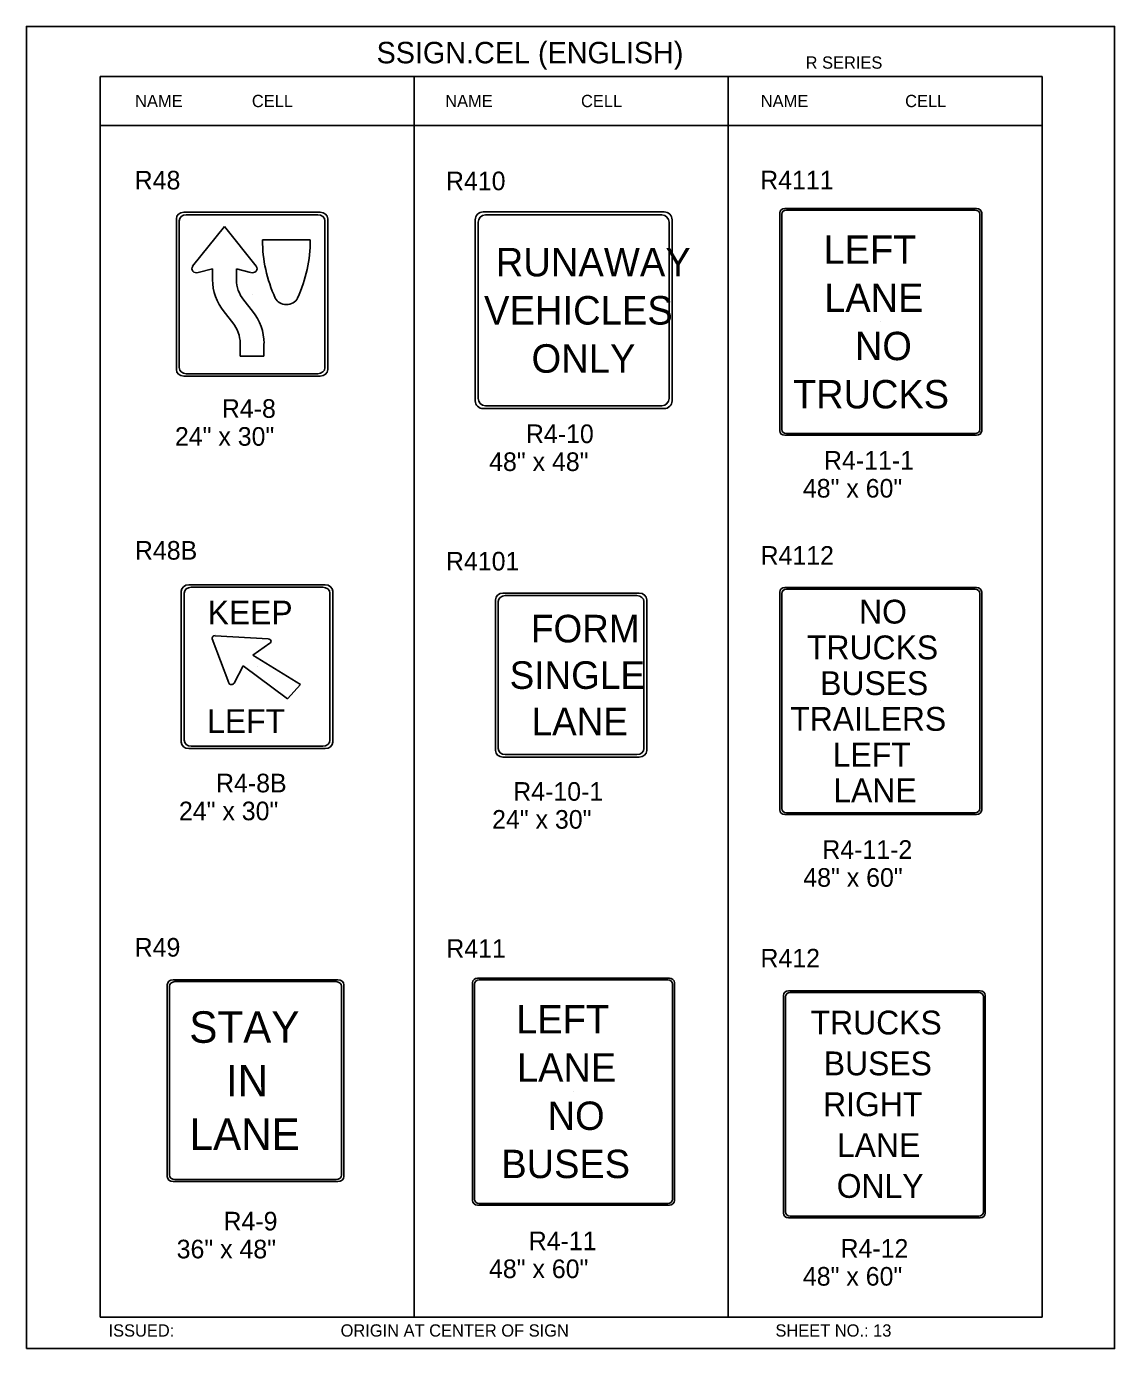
# Model space of a CAD drawing. Extents: x -5299 to 22597, y -19549 to -1808.
# Drawn here: x -5299 to -4598, y -5466 to -4614 of the extents above; entities that cross this region are included whole.
import ezdxf

# ---------------------------------------------------------------- set-up
doc = ezdxf.new("R2010")
doc.units = 0
for name, color, linetype in [('Level 1', 7, 'Continuous'), ('Level 2', 7, 'Continuous'), ('Level 3', 7, 'Continuous'), ('Level 63', 7, 'Continuous')]:
    doc.layers.add(name, color=color, linetype=linetype)

msp = doc.modelspace()

# ---------------------------------------------------------------- linework, layer by layer
at = {"layer": 'Level 1'}
for p, q in [((-4644.53, -4645.77), (-5251.55, -4645.77)), ((-5251.55, -4645.77), (-5251.55, -5445.77)), ((-5049.21, -4645.77), (-5049.21, -5445.77)), ((-4846.87, -4645.77), (-4846.87, -5445.77)), ((-4644.53, -4645.77), (-4644.53, -5445.77)), ((-4644.53, -4677.44), (-5251.55, -4677.44)), ((-5200.66, -4833.56), (-5200.66, -4738.86)), ((-5196.15, -4734.95), (-5111.26, -4734.95)), ((-5106.75, -4738.86), (-5106.75, -4833.56)), ((-5003.32, -4735.07), (-4889.68, -4735.07)), ((-4812.44, -4873.4), (-4812.44, -4734.69)), ((-4809.43, -4731.98), (-4687.82, -4731.98)), ((-4684.81, -4734.69), (-4684.81, -4873.4)), ((-5171.46, -4742.49), (-5191.98, -4768.19)), ((-5151.01, -4768.19), (-5171.46, -4742.49)), ((-5008.01, -4853.41), (-5008.01, -4739.77)), ((-4884.98, -4739.77), (-4884.98, -4853.41)), ((-5116.22, -4751.22), (-5146.96, -4751.22)), ((-5188.39, -4772.32), (-5179.18, -4769.88)), ((-5179.18, -4769.88), (-5179.18, -4776.85)), ((-5163.81, -4776.85), (-5163.81, -4769.88)), ((-5163.81, -4769.88), (-5154.6, -4772.32)), ((-5153.43, -4797.13), (-5159.05, -4790.1)), ((-5153.71, -4786.21), (-5153.71, -4786.21)), ((-5171.77, -4797.61), (-5166.15, -4804.64)), ((-4946.5, -4796.59), (-4946.5, -4796.59)), ((-4748.63, -4804.05), (-4748.63, -4804.05)), ((-5161.39, -4817.89), (-5161.39, -4826.21)), ((-5146.02, -4826.21), (-5146.02, -4817.89)), ((-5161.39, -4826.21), (-5146.02, -4826.21)), ((-5111.26, -4837.47), (-5196.15, -4837.47)), ((-5008.01, -4853.41), (-5008.01, -4853.41)), ((-4889.68, -4858.1), (-5003.32, -4858.1)), ((-4687.82, -4876.11), (-4809.43, -4876.11)), ((-5192.95, -4975.1), (-5108.06, -4975.1)), ((-4809.43, -4976.41), (-4687.82, -4976.41)), ((-5197.46, -5073.72), (-5197.46, -4979.01)), ((-5103.55, -4979.01), (-5103.55, -5073.72)), ((-4995.1, -5079.13), (-4995.1, -4984.42)), ((-4990.59, -4980.51), (-4905.7, -4980.51)), ((-4901.19, -4984.42), (-4901.19, -5079.13)), ((-4812.44, -5117.82), (-4812.44, -4979.11)), ((-4684.81, -4979.11), (-4684.81, -5117.82)), ((-5179.33, -5008.44), (-5168.72, -5036.84)), ((-5143.28, -5008.44), (-5177.46, -5006.41)), ((-5153.11, -5018.98), (-5142.19, -5011.28)), ((-5122.53, -5037.78), (-5153.11, -5018.98)), ((-5165.28, -5036.97), (-5159.35, -5025.88)), ((-5159.35, -5025.88), (-5130.95, -5046.98)), ((-5150.5, -5026.36), (-5150.5, -5026.36)), ((-4948.14, -5031.77), (-4948.14, -5031.77)), ((-5130.95, -5046.98), (-5122.53, -5037.78)), ((-4748.63, -5048.47), (-4748.63, -5048.47)), ((-5108.06, -5077.62), (-5192.95, -5077.62)), ((-4905.7, -5083.03), (-4990.59, -5083.03)), ((-4687.82, -5120.53), (-4809.43, -5120.53)), ((-5206.97, -5354.03), (-5206.97, -5232.42)), ((-5203.46, -5229.41), (-5099.5, -5229.41)), ((-5095.99, -5232.42), (-5095.99, -5354.03)), ((-5010.41, -5369.65), (-5010.41, -5230.94)), ((-5007.4, -5228.24), (-4885.79, -5228.24)), ((-4882.78, -5230.94), (-4882.78, -5369.65)), ((-4811.32, -5378.68), (-4811.32, -5238.23)), ((-4810.11, -5377.81), (-4810.11, -5239.1)), ((-4808.06, -5235.31), (-4684.52, -5235.31)), ((-4807.1, -5236.4), (-4685.49, -5236.4)), ((-4682.48, -5239.1), (-4682.48, -5377.81)), ((-4681.27, -5238.23), (-4681.27, -5378.68)), ((-5151.48, -5293.23), (-5151.48, -5293.23)), ((-4946.6, -5300.3), (-4946.6, -5300.3)), ((-4746.29, -5308.46), (-4746.29, -5308.46)), ((-5099.5, -5357.04), (-5203.46, -5357.04)), ((-4885.79, -5372.36), (-5007.4, -5372.36)), ((-4684.52, -5381.61), (-4808.06, -5381.61)), ((-4685.49, -5380.52), (-4807.1, -5380.52)), ((-5251.55, -5445.77), (-4644.53, -5445.77))]:
    msp.add_line(p, q, dxfattribs=at)
for centre, start, end in [((-5003.32, -4739.77), 90, 180), ((-4889.68, -4739.77), 0, 90), ((-5003.32, -4853.41), 180, 270), ((-4889.68, -4853.41), 270, 0)]:
    msp.add_arc(centre, 4.69, start, end, dxfattribs=at)
for centre, major_axis, ratio, start_param, end_param in [((-5196.15, -4738.86), (-4.51, 0), 0.866667, 4.712389, 6.283185), ((-5111.26, -4738.86), (-4.51, 0), 0.866667, 3.141593, 4.712389), ((-4809.43, -4734.69), (-3.01, 0), 0.9, 4.712389, 6.283185), ((-4687.82, -4734.69), (-3.01, 0), 0.9, 3.141593, 4.712389), ((-5031.47, -4751.56), (-115.48, 0), 0.866667, 6.279909, 6.663033), ((-5231.25, -4751.64), (115.05, 0), 0.866667, 5.902613, 6.287187), ((-5189.26, -4769.66), (-3.2, 0), 0.866667, 5.710118, 8.143254), ((-5153.67, -4769.66), (3.2, 0), 0.866667, 4.423116, 6.856252), ((-5136.67, -4776.83), (42.49, 0), 0.866667, 3.14236, 3.740294), ((-5136.89, -4776.86), (26.88, 0), 0.866667, 3.141339, 3.744924), ((-5131.57, -4786.23), (7.68, 0), 0.866667, 3.517117, 5.907661), ((-5188.29, -4817.88), (-42.29, 0), 0.866667, 3.141593, 3.744195), ((-5188.15, -4817.87), (26.77, 0), 0.866667, 6.282648, 6.891725), ((-5196.15, -4833.56), (4.51, 0), 0.866667, 3.141593, 4.712389), ((-5111.26, -4833.56), (4.51, 0), 0.866667, 4.712389, 6.283185), ((-4809.43, -4873.4), (3.01, 0), 0.9, 3.141593, 4.712389), ((-4687.82, -4873.4), (3.01, 0), 0.9, 4.712389, 6.283185), ((-5192.95, -4979.01), (-4.51, 0), 0.866667, 4.712389, 6.283185), ((-5108.06, -4979.01), (-4.51, 0), 0.866667, 3.141593, 4.712389), ((-4809.43, -4979.11), (-3.01, 0), 0.9, 4.712389, 6.283185), ((-4687.82, -4979.11), (-3.01, 0), 0.9, 3.141593, 4.712389), ((-4990.59, -4984.42), (-4.51, 0), 0.866667, 4.712389, 6.283185), ((-4905.7, -4984.42), (-4.51, 0), 0.866667, 3.141593, 4.712389), ((-5177.58, -5007.97), (-1.89, 0), 0.866667, 4.637334, 6.588204), ((-5143.3, -5010.03), (1.88, 0), 0.866667, 5.375922, 7.805476), ((-5166.98, -5036.3), (1.88, 0), 0.866667, 3.443944, 5.86527), ((-5192.95, -5073.72), (4.51, 0), 0.866667, 3.141593, 4.712389), ((-5108.06, -5073.72), (4.51, 0), 0.866667, 4.712389, 6.283185), ((-4990.59, -5079.13), (4.51, 0), 0.866667, 3.141593, 4.712389), ((-4905.7, -5079.13), (4.51, 0), 0.866667, 4.712389, 6.283185), ((-4809.43, -5117.83), (3.01, 0), 0.9, 3.141593, 4.712389), ((-4687.82, -5117.83), (3.01, 0), 0.9, 4.712389, 6.283185), ((-5203.46, -5232.42), (-3.51, 0), 0.857082, 4.712389, 6.283185), ((-5099.5, -5232.42), (-3.51, 0), 0.857082, 3.141593, 4.712389), ((-5007.4, -5230.94), (-3.01, 0), 0.9, 4.712389, 6.283185), ((-4885.79, -5230.94), (-3.01, 0), 0.9, 3.141593, 4.712389), ((-4808.06, -5238.24), (-3.25, 0), 0.9, 4.712389, 6.283185), ((-4807.1, -5239.1), (-3.01, 0), 0.9, 4.712389, 6.283185), ((-4685.49, -5239.1), (-3.01, 0), 0.9, 3.141593, 4.712389), ((-4684.52, -5238.24), (-3.25, 0), 0.9, 3.141593, 4.712389), ((-5203.46, -5354.03), (3.51, 0), 0.857082, 3.141593, 4.712389), ((-5099.5, -5354.03), (3.51, 0), 0.857082, 4.712389, 6.283185), ((-5007.4, -5369.66), (3.01, 0), 0.9, 3.141593, 4.712389), ((-4885.79, -5369.66), (3.01, 0), 0.9, 4.712389, 6.283185), ((-4807.1, -5377.81), (3.01, 0), 0.9, 3.141593, 4.712389), ((-4685.49, -5377.81), (3.01, 0), 0.9, 4.712389, 6.283185), ((-4808.06, -5378.68), (3.25, 0), 0.9, 3.141593, 4.712389), ((-4684.52, -5378.68), (3.25, 0), 0.9, 4.712389, 6.283185)]:
    msp.add_ellipse(centre, major_axis=major_axis, ratio=ratio, start_param=start_param, end_param=end_param, dxfattribs=at)
at = {"layer": 'Level 3'}
for p, q in [((-5202.47, -4834.82), (-5202.47, -4737.61)), ((-5197.6, -4733.38), (-5109.82, -4733.38)), ((-5104.94, -4737.61), (-5104.94, -4834.82)), ((-5009.89, -4854.91), (-5009.89, -4738.26)), ((-5004.82, -4733.19), (-4888.17, -4733.19)), ((-4883.1, -4738.26), (-4883.1, -4854.91)), ((-4813.65, -4733.82), (-4813.65, -4874.27)), ((-4686.86, -4730.9), (-4810.4, -4730.9)), ((-4683.61, -4874.27), (-4683.61, -4733.82)), ((-5109.82, -4839.04), (-5197.6, -4839.04)), ((-4888.17, -4859.98), (-5004.82, -4859.98)), ((-4810.4, -4877.19), (-4686.86, -4877.19)), ((-5199.27, -4977.76), (-5199.27, -5074.97)), ((-5106.61, -4973.53), (-5194.39, -4973.53)), ((-5101.74, -5074.97), (-5101.74, -4977.76)), ((-4810.4, -4975.32), (-4686.86, -4975.32)), ((-4996.91, -5080.38), (-4996.91, -4983.17)), ((-4992.03, -4978.94), (-4904.26, -4978.94)), ((-4899.38, -4983.17), (-4899.38, -5080.38)), ((-4813.65, -5118.69), (-4813.65, -4978.25)), ((-4683.61, -4978.25), (-4683.61, -5118.69)), ((-5194.39, -5079.19), (-5106.61, -5079.19)), ((-4904.26, -5084.6), (-4992.03, -5084.6)), ((-4686.86, -5121.62), (-4810.4, -5121.62)), ((-5208.38, -5355), (-5208.38, -5231.46)), ((-5204.58, -5228.21), (-5098.38, -5228.21)), ((-5094.58, -5231.46), (-5094.58, -5355)), ((-5011.62, -5370.52), (-5011.62, -5230.08)), ((-5008.37, -5227.15), (-4884.83, -5227.15)), ((-4881.58, -5230.08), (-4881.58, -5370.52)), ((-4811.32, -5378.68), (-4811.32, -5238.23)), ((-4808.06, -5235.31), (-4684.52, -5235.31)), ((-4681.27, -5238.23), (-4681.27, -5378.68)), ((-5098.38, -5358.25), (-5204.58, -5358.25)), ((-4884.83, -5373.45), (-5008.37, -5373.45)), ((-4684.52, -5381.61), (-4808.06, -5381.61))]:
    msp.add_line(p, q, dxfattribs=at)
for centre, start, end in [((-5004.82, -4738.26), 90, 180), ((-4888.17, -4738.26), 0, 90), ((-5004.82, -4854.91), 180, 270), ((-4888.17, -4854.91), 270, 0)]:
    msp.add_arc(centre, 5.07, start, end, dxfattribs=at)
for centre, major_axis, ratio, start_param, end_param in [((-5197.6, -4737.61), (-4.88, 0), 0.866667, 4.712389, 6.283185), ((-5109.82, -4737.61), (-4.88, 0), 0.866667, 3.141593, 4.712389), ((-4810.4, -4733.82), (-3.25, 0), 0.9, 4.712389, 6.283185), ((-4686.86, -4733.82), (-3.25, 0), 0.9, 3.141593, 4.712389), ((-5197.6, -4834.82), (4.88, 0), 0.866667, 3.141593, 4.712389), ((-5109.82, -4834.82), (4.88, 0), 0.866667, 4.712389, 6.283185), ((-4810.4, -4874.27), (3.25, 0), 0.9, 3.141593, 4.712389), ((-4686.86, -4874.27), (3.25, 0), 0.9, 4.712389, 6.283185), ((-5194.39, -4977.76), (-4.88, 0), 0.866667, 4.712389, 6.283185), ((-5106.61, -4977.76), (-4.88, 0), 0.866667, 3.141593, 4.712389), ((-4810.4, -4978.25), (-3.25, 0), 0.9, 4.712389, 6.283185), ((-4686.86, -4978.25), (-3.25, 0), 0.9, 3.141593, 4.712389), ((-4992.03, -4983.17), (-4.88, 0), 0.866667, 4.712389, 6.283185), ((-4904.26, -4983.17), (-4.88, 0), 0.866667, 3.141593, 4.712389), ((-5194.39, -5074.97), (4.88, 0), 0.866667, 3.141593, 4.712389), ((-5106.61, -5074.97), (4.88, 0), 0.866667, 4.712389, 6.283185), ((-4992.03, -5080.38), (4.88, 0), 0.866667, 3.141593, 4.712389), ((-4904.26, -5080.38), (4.88, 0), 0.866667, 4.712389, 6.283185), ((-4810.4, -5118.69), (3.25, 0), 0.9, 3.141593, 4.712389), ((-4686.86, -5118.69), (3.25, 0), 0.9, 4.712389, 6.283185), ((-5204.58, -5231.46), (-3.79, 0), 0.857082, 4.712389, 6.283185), ((-5098.38, -5231.46), (-3.79, 0), 0.857082, 3.141593, 4.712389), ((-5008.37, -5230.08), (-3.25, 0), 0.9, 4.712389, 6.283185), ((-4884.83, -5230.08), (-3.25, 0), 0.9, 3.141593, 4.712389), ((-4808.06, -5238.24), (-3.25, 0), 0.9, 4.712389, 6.283185), ((-4684.52, -5238.24), (-3.25, 0), 0.9, 3.141593, 4.712389), ((-5204.58, -5355), (3.79, 0), 0.857082, 3.141593, 4.712389), ((-5098.38, -5355), (3.79, 0), 0.857082, 4.712389, 6.283185), ((-5008.37, -5370.52), (3.25, 0), 0.9, 3.141593, 4.712389), ((-4884.83, -5370.52), (3.25, 0), 0.9, 4.712389, 6.283185), ((-4808.06, -5378.68), (3.25, 0), 0.9, 3.141593, 4.712389), ((-4684.52, -5378.68), (3.25, 0), 0.9, 4.712389, 6.283185)]:
    msp.add_ellipse(centre, major_axis=major_axis, ratio=ratio, start_param=start_param, end_param=end_param, dxfattribs=at)
at = {"layer": 'Level 63'}
msp.add_lwpolyline([(-5299.05, -5465.96), (-4598.01, -5465.96), (-4598.01, -4613.58), (-5299.05, -4613.58)], close=True, dxfattribs=at)

# ---------------------------------------------------------------- texts
at = {"layer": 'Level 1'}
for s, height, p in [('LEFT', 18.287, (-4785.5, -4766.56)), ('RUNAWAY', 18.385, (-4996.69, -4774.72)), ('LANE', 18.287, (-4785.03, -4797.64)), ('VEHICLES', 18.385, (-5004.24, -4805.78)), ('NO', 18.287, (-4765.27, -4828.73)), ('ONLY', 18.385, (-4973.63, -4836.84)), ('TRUCKS', 18.287, (-4805.18, -4859.82)), ('KEEP', 15.321, (-5182.24, -4999.11)), ('NO', 15.361, (-4762.6, -4998.55)), ('FORM', 17.779, (-4974.01, -5010.69)), ('TRUCKS', 15.361, (-4796.13, -5021.59)), ('SINGLE', 17.779, (-4987.73, -5040.66)), ('BUSES', 15.361, (-4787.67, -5044.63)), ('LEFT', 15.321, (-5182.59, -5069.08)), ('LANE', 17.779, (-4973.62, -5070.63)), ('TRAILERS', 15.361, (-4806.93, -5067.67)), ('LEFT', 15.361, (-4779.6, -5090.71)), ('LANE', 15.361, (-4779.2, -5113.75)), ('STAY', 20.319, (-5194.13, -5268.84)), ('LEFT', 18.287, (-4983.47, -5262.81)), ('TRUCKS', 15.361, (-4793.8, -5263.47)), ('LANE', 18.287, (-4982.99, -5293.9)), ('BUSES', 15.361, (-4785.34, -5289.8)), ('IN', 20.319, (-5170.52, -5303.39)), ('RIGHT', 15.361, (-4785.74, -5316.14)), ('NO', 18.287, (-4963.23, -5324.99)), ('LANE', 20.319, (-5193.95, -5337.93)), ('LANE', 15.361, (-4776.87, -5342.47)), ('BUSES', 18.287, (-4993.07, -5356.07)), ('ONLY', 15.361, (-4777, -5368.8))]:
    msp.add_text(s, height=height, dxfattribs=at).set_placement(p)
at = {"layer": 'Level 2'}
for s, p in [('R48', (-5229.31, -4718.68)), ('R410', (-5028.76, -4719.19)), ('R4111', (-4826.31, -4718.62)), ('R48B', (-5229.17, -4957.34)), ('R4101', (-5028.76, -4964.32)), ('R4112', (-4826.08, -4960.62)), ('R49', (-5229.32, -5213.26)), ('R411', (-5028.53, -5214.03)), ('R412', (-4826.14, -5220.27))]:
    msp.add_text(s, height=12, dxfattribs=at).set_placement(p)
at = {"layer": 'Level 3'}
for s, height, p in [('SSIGN.CEL (ENGLISH)', 13.8566, (-5073.47, -4637.38)), ('R SERIES', 7.918, (-4797.03, -4640.82)), ('NAME', 7.918, (-5229.05, -4665.6)), ('CELL', 7.918, (-5153.82, -4665.6)), ('NAME', 7.918, (-5029.24, -4665.6)), ('CELL', 7.918, (-4941.74, -4665.6)), ('NAME', 7.918, (-4825.94, -4665.6)), ('CELL', 7.918, (-4732.92, -4665.6)), ('R4-8', 12, (-5173.16, -4865.9)), ('24" x 30"', 12, (-5203.4, -4883.9)), ('R4-10', 12, (-4977.24, -4882.19)), ('48" x 48"', 12, (-5000.95, -4900.19)), ('R4-11-1', 12, (-4785.21, -4899.33)), ('48" x 60"', 12, (-4798.81, -4917.33)), ('R4-8B', 12, (-5176.9, -5107.36)), ('R4-10-1', 12, (-4985.43, -5112.79)), ('24" x 30"', 12, (-5200.81, -5125.36)), ('24" x 30"', 12, (-4999.04, -5130.79)), ('R4-11-2', 12, (-4786.3, -5150.23)), ('48" x 60"', 12, (-4798.53, -5168.23)), ('R4-9', 12, (-5172.09, -5389.81)), ('R4-11', 12, (-4975.43, -5402.53)), ('R4-12', 12, (-4774.56, -5407.39)), ('36" x 48"', 12, (-5202.28, -5407.81)), ('48" x 60"', 12, (-5001.04, -5420.53)), ('48" x 60"', 12, (-4798.8, -5425.39)), ('ISSUED:', 7.918, (-5246.18, -5458.26)), ('ORIGIN AT CENTER OF SIGN', 7.9181, (-5096.65, -5458.26)), ('SHEET NO.: 13', 7.918, (-4816.49, -5458.26))]:
    msp.add_text(s, height=height, dxfattribs=at).set_placement(p)

doc.saveas('drawing.dxf')
